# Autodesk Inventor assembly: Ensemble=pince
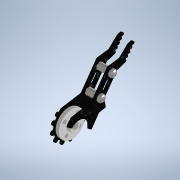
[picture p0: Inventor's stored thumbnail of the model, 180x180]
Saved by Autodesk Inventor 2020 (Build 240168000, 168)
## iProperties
Created: 2021-10
Part Number: Ensemble=pince
Document SubType Name: Assembly
Designer: bruno
Author: bruno
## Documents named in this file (5)
- C:\Users\bruno\Documents\1-Cours-2021-22\1SI\Challenge-2021\Pince-Inventor\Ensemble=pince.iam
- C:\Users\bruno\Documents\1-Cours-2021-22\1SI\Challenge-2021\Pince-Inventor\Ensemble-doigt.iam
- C:\Users\bruno\Documents\1-Cours-2021-22\1SI\Challenge-2021\Pince-Inventor\pince-2.ipt
- C:\Users\bruno\Documents\1-Cours-2021-22\1SI\Challenge-2021\Pince-Inventor\embout-servo.ipt
- C:\Users\bruno\Documents\Inventor\Content Center Files\R2020\fr-FR\ANSI B18.6.7M(01)\ANSI B18.6.7M - M3x0,5 x 5(5).ipt
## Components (6 placed, 4 different names)
1. Ensemble-doigt:1 [sub-assembly] — Logement:1, Placage:1, Placage:2, Angle:1, Placage:8
2. pince-2:1 — Logement:1, Placage:3, Placage:4, Placage:5, Placage:6, Angle:1
3. embout-servo:1 — Placage:1, Placage:2, Placage:7
4. Vis à tête tronconique à empreinte cruciforme - Type IA - Métrique M3x0,5 x 5:1 — Placage:3, Placage:4
5. Vis à tête tronconique à empreinte cruciforme - Type IA - Métrique M3x0,5 x 5:2 — Placage:5, Placage:6
6. Vis à tête tronconique à empreinte cruciforme - Type IA - Métrique M3x0,5 x 5:3 — Placage:7, Placage:8
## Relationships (10: Mate 8, Insert 1, Angle 1)
- Logement:1 [Insert]: Ensemble-doigt:1 ↔ pince-2:1
- Placage:1 [Mate]: Ensemble-doigt:1 ↔ embout-servo:1
- Placage:2 [Mate]: Ensemble-doigt:1 ↔ embout-servo:1
- Placage:3 [Mate]: pince-2:1 ↔ Vis à tête tronconique à empreinte cruciforme - Type IA - Métrique M3x0,5 x 5:1
- Placage:4 [Mate]: pince-2:1 ↔ Vis à tête tronconique à empreinte cruciforme - Type IA - Métrique M3x0,5 x 5:1
- Placage:5 [Mate]: pince-2:1 ↔ Vis à tête tronconique à empreinte cruciforme - Type IA - Métrique M3x0,5 x 5:2
- Placage:6 [Mate]: pince-2:1 ↔ Vis à tête tronconique à empreinte cruciforme - Type IA - Métrique M3x0,5 x 5:2
- Angle:1: Ensemble-doigt:1 ↔ pince-2:1
- Placage:7 [Mate]: embout-servo:1 ↔ Vis à tête tronconique à empreinte cruciforme - Type IA - Métrique M3x0,5 x 5:3
- Placage:8 [Mate]: Ensemble-doigt:1 ↔ Vis à tête tronconique à empreinte cruciforme - Type IA - Métrique M3x0,5 x 5:3
